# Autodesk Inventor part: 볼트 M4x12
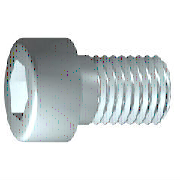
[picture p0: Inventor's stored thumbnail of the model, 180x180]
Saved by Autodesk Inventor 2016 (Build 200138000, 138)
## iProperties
IsCustomPart: 0
Created: 2015-12
Part Number: 볼트 M4x12
Material: 강철, 연강
Description: 6각머리 태핑 나사
Document SubType Name: Modeling
Standard: KS B 1003
Designer: mdu
Standards Organization: KS
Language: ko-KR
Size Designation: M 4 x 12
Categories: <MemberInstance><Categories><Category DisplayName="조임쇠" InternalName="e4da775c-781d-43d5-af7c-5136215cf5a6" Mnemonic="FSTN"><Category DisplayName="볼트" InternalN
Density: 7.86 g/cm^3
Mass: 2.23465 g
Surface Area: 3.30853 cm^2
Volume: 0.284306 cm^3
Appearance: 진녹색
Author: mdu
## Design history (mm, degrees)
sketch "스케치1"
  geometry: L1 (-1, 0)-(12, 0); L2 (12, 0)-(12, 2); L3 (12, 2)-(1.75, 2); L4 (1.75, 2)-(1.32, 2); L5 (1.32, 2)-(0, 2); L6 (0, 2)-(0, 3.5); L7 (0, 3.5)-(-4, 3.5); L8 (-4, 3.5)-(-4, 1.732); L9 (-4, 1.732)-(-2, 1.732); L10 (-2, 1.732)-(-1, 0); L11 (-7.2, 0)-(15.2, 0) reference; L12 (0, -0.7)-(0, 4.2) reference; L13 (1.75, 2)-(0, 2)
  constraints: 22 end point, 6 parallel, 2 collinear, 2 perpendicular, 1 horizontal, 1 point on line
  dimensions: "d1" = 10.25 distance from line of L3.end L2 (= GEL); "d2" = 0.42952 distance of L4.end L3.end (computed from GAL); "d3" = 4 distance between parallel lines of L8 L6 (= KOH); "d4" = 2 distance of L8.end L9.end (= INTI); "d5" = 60 deg angle of L10 L1; "d6" = 4 diameter of L3 L1 (= GD); "d7" = 4 diameter of L5 L1 (= BDM); "d8" = 3.4641 diameter of L9 L1 (= 1.1547 x SW); "d9" = 7 diameter of L7 L1 (= KOD); "d26" = 12 distance between parallel lines of L12 L2 (= NLG)
revolve "본체" sketch "스케치1" stored, may be unused: angle "d10" = 90 deg
sketch "스케치2"
  geometry: L1 (0, -4.9)-(0, 4.9) reference; L2 (-4.9, 0)-(4.9, 0) reference; L3 (1.732, 0)-(0.866, -1.5); L4 (0.866, -1.5)-(-0.866, -1.5); L5 (-0.866, -1.5)-(-1.732, 0); L6 (-1.732, 0)-(-0.866, 1.5); L7 (-0.866, 1.5)-(0.866, 1.5); L8 (0.866, 1.5)-(1.732, 0); 2 further points
  constraints: 12 end point, 1 coincident, 1 horizontal alignment, 1 point on line, 12 other
extrude "슬롯" join sketch "스케치2" stored distance "d11" = 10; taper "d12" = 0 deg
workplane "Work Plane1"
fillet "Fillet2" dims "d30" = 0.1 (= R)
body "Solid1"
fillet "모깎기1" dims "d17" = 0.4 (= RR)
feature "스레드" dims "d13" = 10.25 (= GEL), "d14" = 0
chamfer "모따기1" distance "d15" = 0.42941 (= -0.5 x SPD + 0.5 x GD); stored, may be unused: second distance "d16" = 0.42941 (= GUL), angle "d27" = 45 deg
other parameters: "GD" = 4 (= NND) [user parameter; used in 2 equation terms], "NLG" = 12 [user parameter; used in 1 equation term], "GEL" = 10.25 [user parameter; used in 2 equation terms], "KOD" = 7 [user parameter; used in 1 equation term], "KOH" = 4 [user parameter; used in 1 equation term], "INTI" = 2 [user parameter; used in 1 equation term], "GAL" = 0.42941 (= 0.61345 x PTC) [user parameter; used in 1 equation term], "GUL" = 0.42941 (= 0.61345 x PTC) [user parameter; used in 1 equation term], "BDM" = 4 (= NND) [user parameter; used in 1 equation term], "SW" = 3 [user parameter; used in 2 equation terms], "RR" = 0.4 [user parameter; used in 1 equation term], "SPD" = 3.14117 (= NND - 1.2269 x PTC) [user parameter; used in 1 equation term], "d19" = 0, "d28" = 0, "d29" = 0, "R" = 0.1 [user parameter; used in 1 equation term], "PHH" = 0.2 [user parameter], "GD1" = 3.14117 (= THREADDIA - 1.2269 x PTC) [user parameter], "THREADDIA" = 4 [user parameter; used in 1 equation term], "FAWI" = 45 deg [user parameter], "TPU" = 14.28571 (computed from PTC) [user parameter], "PTC" = 0.7 [user parameter; used in 5 equation terms], "NND" = 4 [user parameter; used in 3 equation terms], "TOA" = 30 deg [user parameter], "E0" = 3.465 (= 1.155 x SW) [user parameter]
